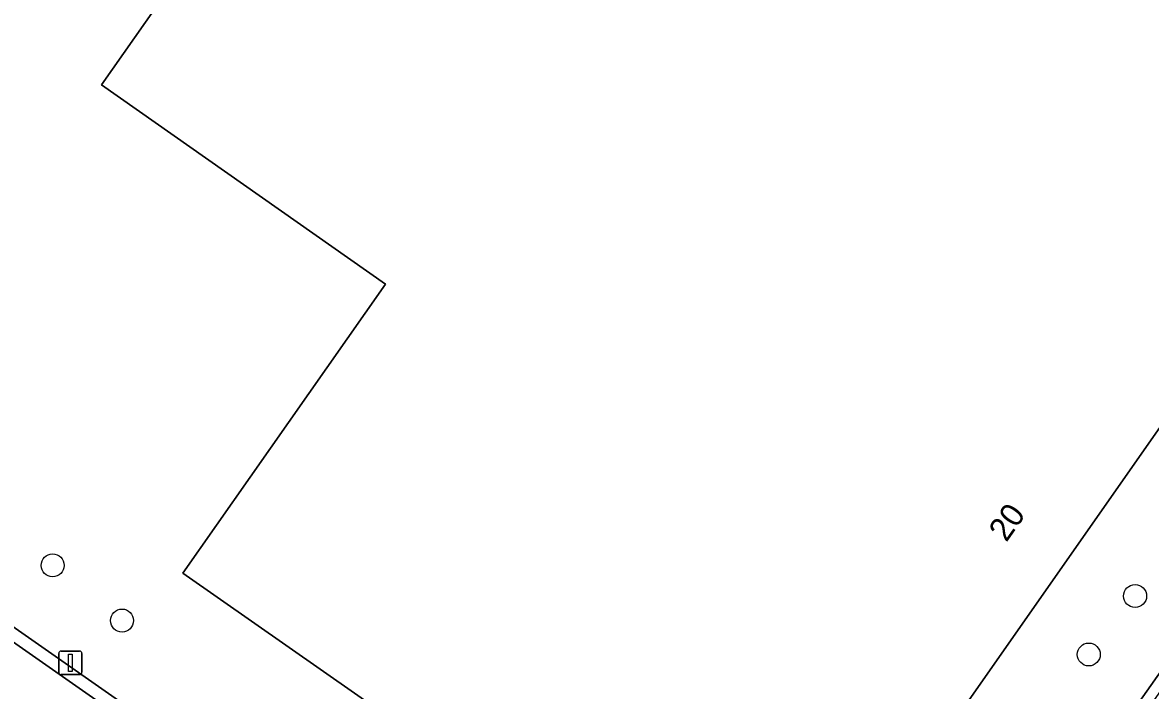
# Model space of a CAD drawing. Extents: x 155018 to 156648, y 383979 to 385733.
# Drawn here: x 155513.44 to 155561.5, y 384726 to 384754.48 of the extents above; entities that cross this region are included whole.
import ezdxf

# ---------------------------------------------------------------- set-up
doc = ezdxf.new("R2010")
doc.units = 0
for name, color, linetype in [('IMGEO_Boom', 7, 'Continuous'), ('IMGEO_Erf', 7, 'Continuous'), ('IMGEO_Lichtmast', 7, 'Continuous'), ('IMGEO_Pand', 7, 'Continuous'), ('IMGEO_Pand_nummerreeks', 7, 'Continuous'), ('IMGEO_Parkeervlak_open', 7, 'Continuous'), ('IMGEO_Voetpad_open', 7, 'Continuous')]:
    doc.layers.add(name, color=color, linetype=linetype)

msp = doc.modelspace()

# ---------------------------------------------------------------- linework, layer by layer
at = {"layer": 'IMGEO_Boom'}
for centre in [(155514.718, 384731.331), (155560.844, 384730.024), (155517.679, 384728.978), (155558.87, 384727.532)]:
    msp.add_circle(centre, 0.489, dxfattribs=at)
at = {"layer": 'IMGEO_Erf'}
for points in [[(155553.633, 384715.232), (155553.739, 384715.172), (155553.747, 384715.183), (155566.056, 384732.66), (155578.198, 384750), (155612.129, 384798.458), (155612.508, 384798.198), (155616.168, 384803.406), (155615.737, 384803.696), (155649.459, 384851.832), (155649.247, 384851.98)], [(155341.136, 384849.344), (155357.104, 384838.097), (155388.182, 384816.31), (155437.864, 384781.52), (155468.111, 384760.264), (155482.743, 384750), (155497.007, 384739.994), (155500, 384737.848), (155500.185, 384737.718), (155505.292, 384734.131), (155525.191, 384720.19), (155529.43, 384717.209), (155537.244, 384711.718), (155537.392, 384711.902)]]:
    msp.add_lwpolyline(points, dxfattribs=at)
msp.add_lwpolyline([(155567.254, 384753.592), (155571.349, 384750.724), (155570.843, 384750), (155551.094, 384721.759), (155550.46, 384722.203), (155548.26, 384719.057), (155548.864, 384718.635), (155545.279, 384713.508), (155520.268, 384730.998), (155523.134, 384735.096), (155528.902, 384743.323), (155516.799, 384751.818), (155534.25, 384776.701), (155546.358, 384768.223)], close=True, dxfattribs=at)
at = {"layer": 'IMGEO_Lichtmast'}
for p, q in [((155514.978, 384726.777), (155514.978, 384727.577)), ((155514.978, 384727.577), (155514.978, 384726.777)), ((155515.078, 384727.677), (155515.868, 384727.677)), ((155515.868, 384727.677), (155515.078, 384727.677)), ((155515.968, 384727.577), (155515.968, 384726.777)), ((155515.968, 384726.777), (155515.968, 384727.577)), ((155515.868, 384726.677), (155515.078, 384726.677)), ((155515.078, 384726.677), (155515.868, 384726.677))]:
    msp.add_line(p, q, dxfattribs=at)
msp.add_lwpolyline([(155515.398, 384727.552), (155515.548, 384727.552), (155515.548, 384726.802), (155515.398, 384726.802), (155515.398, 384727.552)], dxfattribs=at)
for centre, start, end in [((155515.078, 384727.577), 90, 180), ((155515.078, 384727.577), 90, 180), ((155515.868, 384727.577), 0, 90), ((155515.868, 384727.577), 360, 90), ((155515.078, 384726.777), 180, 270), ((155515.078, 384726.777), 180, 270), ((155515.868, 384726.777), 270, 0), ((155515.868, 384726.777), 270, 0)]:
    msp.add_arc(centre, 0.1, start, end, dxfattribs=at)
at = {"layer": 'IMGEO_Pand'}
msp.add_lwpolyline([(155570.843, 384750), (155571.349, 384750.724), (155567.254, 384753.592), (155546.358, 384768.223), (155534.25, 384776.701), (155516.799, 384751.818), (155528.902, 384743.323), (155523.134, 384735.096), (155520.268, 384730.998), (155545.279, 384713.508), (155548.864, 384718.635), (155548.26, 384719.057), (155550.46, 384722.203), (155551.094, 384721.759)], close=True, dxfattribs=at)
at = {"layer": 'IMGEO_Parkeervlak_open'}
msp.add_lwpolyline([(155523.897, 384720.446), (155505.372, 384733.427), (155503.953, 384731.434), (155522.484, 384718.454)], close=True, dxfattribs=at)
at = {"layer": 'IMGEO_Voetpad_open'}
for points in [[(155596.516, 384775.358), (155600.119, 384780.503), (155611.036, 384796.09), (155611.005, 384796.282), (155612.196, 384797.988), (155612.346, 384797.968), (155612.508, 384798.198), (155612.129, 384798.458), (155578.198, 384750), (155566.056, 384732.66), (155553.747, 384715.183), (155553.739, 384715.172), (155554.237, 384714.972), (155567.524, 384733.965), (155571.397, 384739.494), (155578.755, 384750)], [(155524.877, 384719.759), (155525.191, 384720.19), (155505.292, 384734.131), (155504.984, 384733.699), (155505.372, 384733.427), (155523.897, 384720.446)]]:
    msp.add_lwpolyline(points, close=True, dxfattribs=at)

# ---------------------------------------------------------------- texts
at = {"layer": 'IMGEO_Pand_nummerreeks'}
msp.add_text('20', height=1, rotation=54.9868, dxfattribs=at).set_placement((155555.357, 384732.287))

doc.saveas('drawing.dxf')
